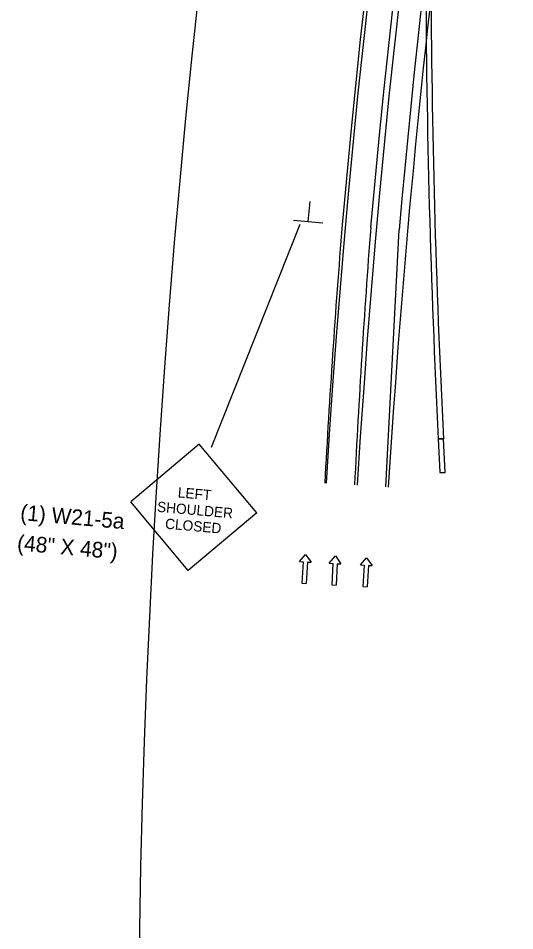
# Model space of a CAD drawing. Extents: x 659657 to 668193, y 633084 to 648639.
# Drawn here: x 661310 to 661501, y 640062.1 to 640412.7 of the extents above; entities that cross this region are included whole.
import ezdxf

# ---------------------------------------------------------------- set-up
doc = ezdxf.new("R2010")
doc.units = 0
for name, color, linetype in [('R_Border Prem', 7, 'Continuous'), ('R_Draft', 7, 'Continuous'), ('R_MOT_Stage 1C', 7, 'Continuous'), ('R_MOT_Stage 1C_Striping', 7, 'Continuous'), ('R_MOT_Stage 2_Striping_PPM', 7, 'Continuous'), ('R_MOT_Stage 3_Striping_PPM', 7, 'Continuous'), ('R_MOT_Stage 4_Striping_PPM', 7, 'Continuous'), ('R_MOT_Stage 5_Striping_PPM', 7, 'Continuous'), ('T_SIGNAL CONTROL CABINET', 7, 'Continuous')]:
    doc.layers.add(name, color=color, linetype=linetype)

msp = doc.modelspace()

# ---------------------------------------------------------------- linework, layer by layer
at = {"layer": 'R_Border Prem'}
msp.add_arc((665219.85, 639999.01), 3863.72, 156.12343, 201.98495, dxfattribs=at)
at = {"layer": 'R_Draft'}
for p, q in [((661421.59, 640334.67), (661422.26, 640342.32)), ((661384.37, 640247.97), (661418.53, 640333.61)), ((661427.15, 640334.02), (661415.94, 640335.01)), ((661379.67, 640249), (661353.31, 640226.91)), ((661401.76, 640222.63), (661379.67, 640249)), ((661375.39, 640200.57), (661353.31, 640226.91)), ((661401.76, 640222.63), (661375.39, 640200.57))]:
    msp.add_line(p, q, dxfattribs=at)
at = {"layer": 'R_MOT_Stage 1C'}
msp.add_line((661471.6, 640251.11), (661473.6, 640251.17), dxfattribs=at)
msp.add_lwpolyline([(661471.6, 640251.11), (661472.23, 640238.12), (661474.23, 640238.22), (661473.6, 640251.17)], close=True, dxfattribs=at)
for centre, radius, start, end in [((665254.05, 640442.69), 3787.3, 180.1951, 182.8995), ((665254.61, 640442.99), 3785.88, 180.20324, 182.90425)]:
    msp.add_arc(centre, radius, start, end, dxfattribs=at)
at = {"layer": 'R_MOT_Stage 1C_Striping'}
msp.add_line((661451.37, 640232.66), (661456.53, 640331.42), dxfattribs=at)
for centre, radius, start, end in [((665219.85, 639999.01), 3799.97, 157.70222, 174.95222), ((665219.85, 639999.01), 3788.97, 157.70222, 174.95222), ((665219.85, 639999.01), 3777.97, 163.39302, 174.95222), ((665222, 640027.58), 3799.7, 175.38418, 176.88418), ((665223.43, 640046.62), 3788.64, 175.67427, 177.17427)]:
    msp.add_arc(centre, radius, start, end, dxfattribs=at)
at = {"layer": 'R_MOT_Stage 2_Striping_PPM'}
for radius, start in [(3798.72, 158.32294), (3786.72, 158.32294), (3774.72, 172.71235)]:
    msp.add_arc((665219.85, 639999.01), radius, start, 176.45222, dxfattribs=at)
at = {"layer": 'R_MOT_Stage 3_Striping_PPM'}
for radius, start in [(3798.72, 158.32294), (3786.72, 158.32294), (3774.72, 172.71235)]:
    msp.add_arc((665219.85, 639999.01), radius, start, 176.45222, dxfattribs=at)
at = {"layer": 'R_MOT_Stage 4_Striping_PPM'}
for radius, start in [(3798.72, 158.32294), (3786.72, 158.32294), (3774.72, 172.71235)]:
    msp.add_arc((665219.85, 639999.01), radius, start, 176.45222, dxfattribs=at)
at = {"layer": 'R_MOT_Stage 5_Striping_PPM'}
for radius, start in [(3798.72, 158.32294), (3786.72, 158.32294), (3774.72, 172.71235)]:
    msp.add_arc((665219.85, 639999.01), radius, start, 176.45222, dxfattribs=at)
at = {"layer": 'T_SIGNAL CONTROL CABINET'}
for p, q in [((661418.15, 640203.92), (661420.55, 640206.72)), ((661420.55, 640206.72), (661422.65, 640203.69)), ((661418.15, 640203.92), (661419.56, 640203.85)), ((661419.56, 640203.85), (661419.12, 640195.59)), ((661421.24, 640203.76), (661420.8, 640195.5)), ((661421.24, 640203.76), (661422.65, 640203.69)), ((661429.64, 640203.3), (661432.04, 640206.09)), ((661429.64, 640203.3), (661431.04, 640203.22)), ((661431.04, 640203.22), (661430.6, 640194.96)), ((661432.04, 640206.09), (661434.13, 640203.06)), ((661432.72, 640203.13), (661432.28, 640194.87)), ((661432.72, 640203.13), (661434.13, 640203.06)), ((661441.62, 640202.64), (661444.02, 640205.44)), ((661444.02, 640205.44), (661446.11, 640202.4)), ((661441.62, 640202.64), (661443.02, 640202.57)), ((661443.02, 640202.57), (661442.58, 640194.3)), ((661444.71, 640202.48), (661444.27, 640194.21)), ((661444.71, 640202.48), (661446.11, 640202.4)), ((661419.12, 640195.59), (661420.8, 640195.5)), ((661430.6, 640194.96), (661432.28, 640194.87)), ((661442.58, 640194.3), (661444.27, 640194.21))]:
    msp.add_line(p, q, dxfattribs=at)

# ---------------------------------------------------------------- texts
at = {"layer": 'R_Draft'}
for s, height, rotation, p in [('LEFT', 3.94, 354.9512, (661371.29, 640228.62)), ('(1) W21-5a', 6, 354.9522, (661310.67, 640219.93)), ('SHOULDER', 3.94, 354.9508, (661363.3, 640223.1)), ('CLOSED', 3.94, 354.9508, (661366.4, 640216.61)), ('(48" X 48")', 6, 354.9522, (661309.46, 640208.25))]:
    msp.add_text(s, height=height, rotation=rotation, dxfattribs=at).set_placement(p)

doc.saveas('drawing.dxf')
